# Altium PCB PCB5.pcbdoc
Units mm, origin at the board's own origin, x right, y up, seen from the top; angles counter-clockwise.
Board outline 122.68 x 122.59 mm, 2 copper layers (Top Layer, Bottom Layer); 24 components, 20 nets, 76 pads, 7 vias.
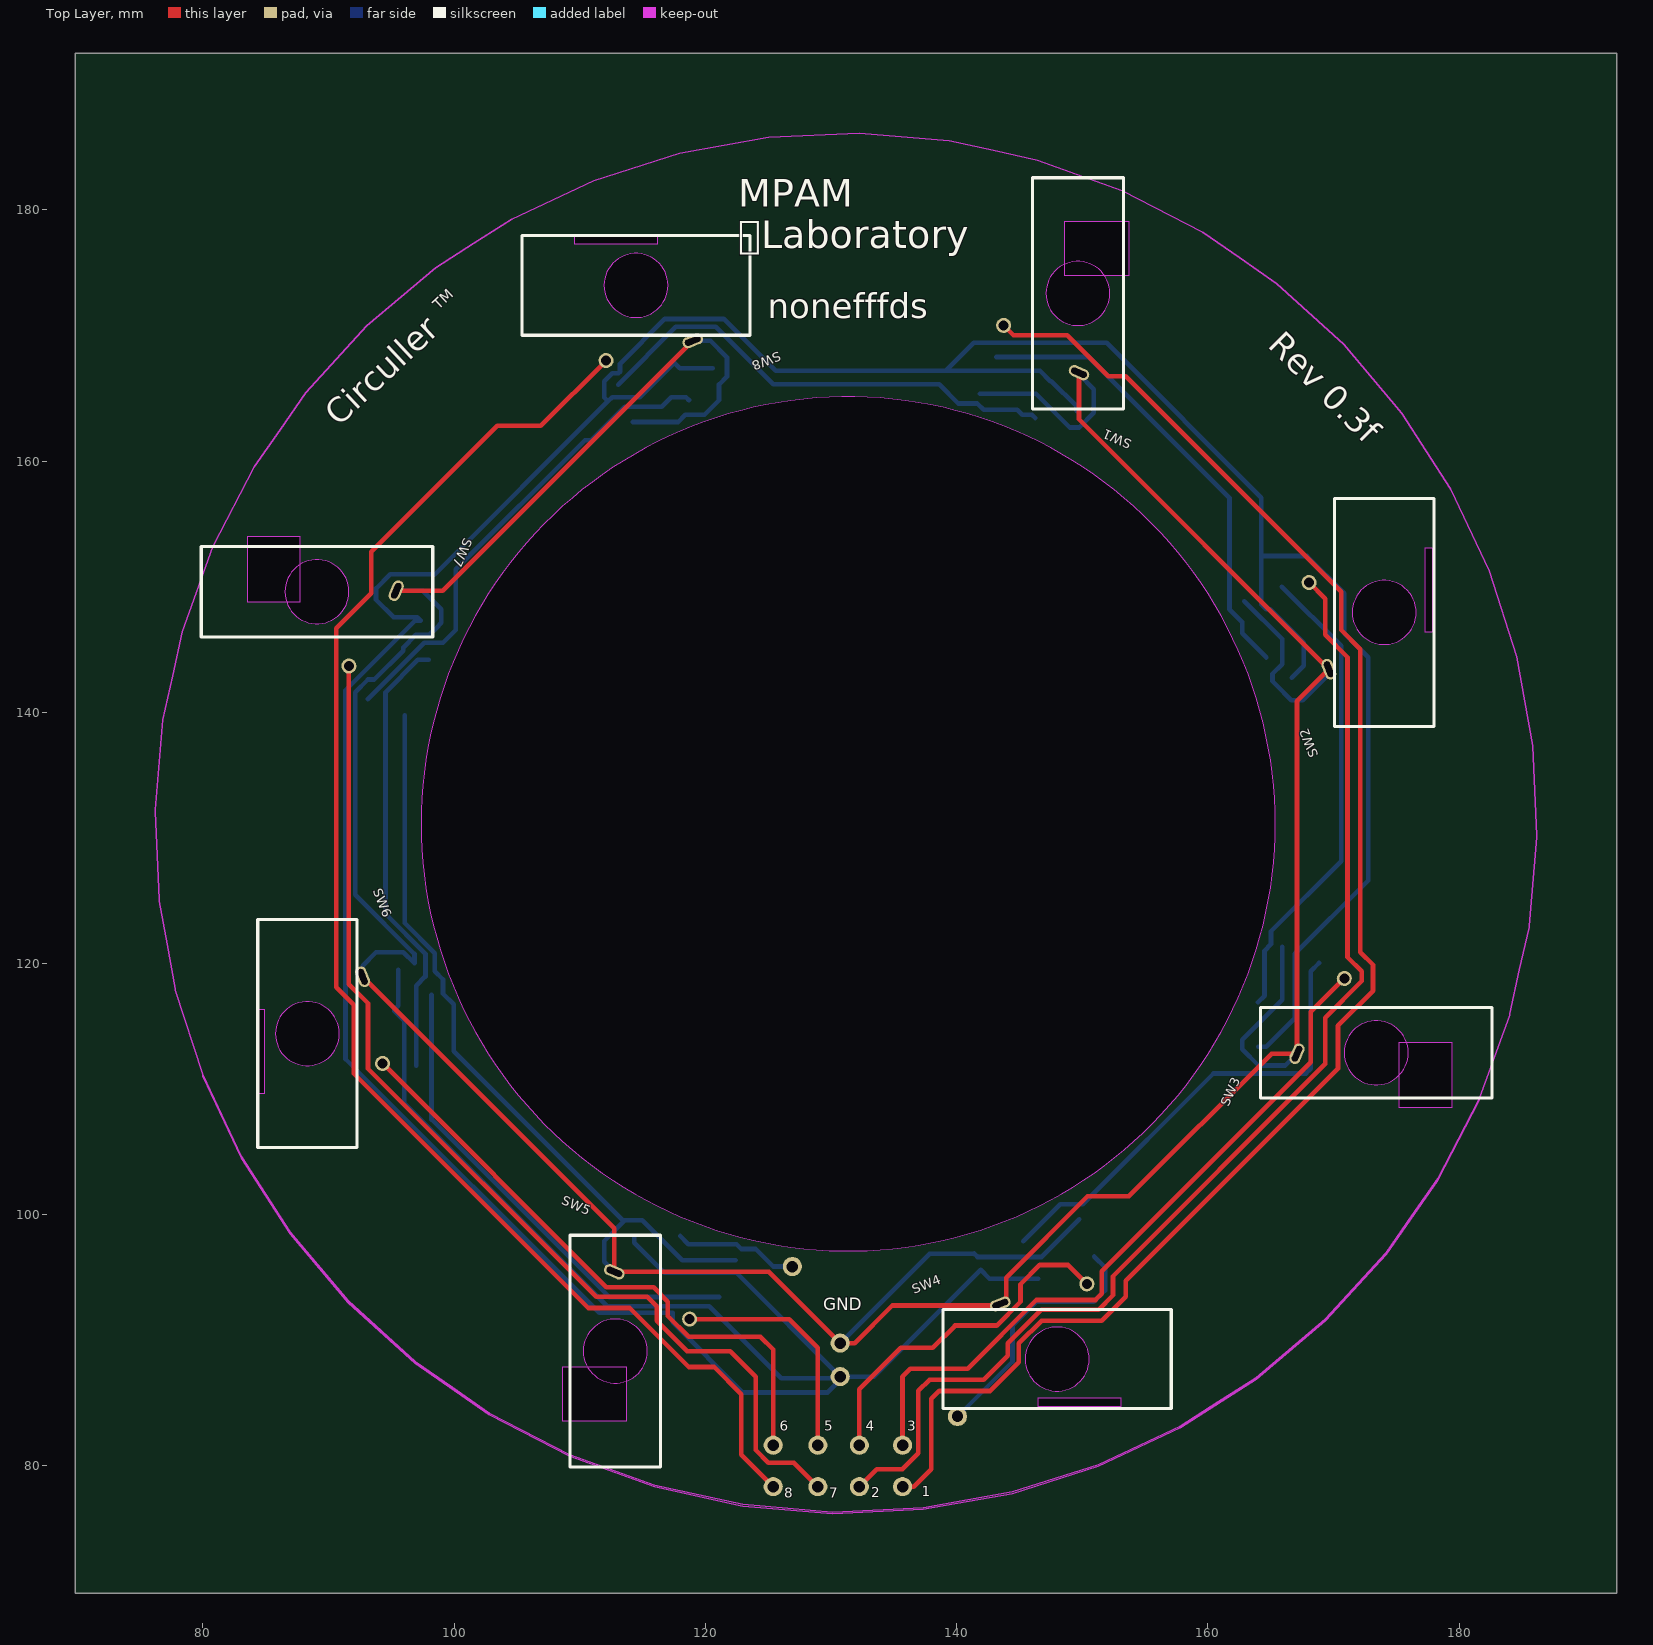
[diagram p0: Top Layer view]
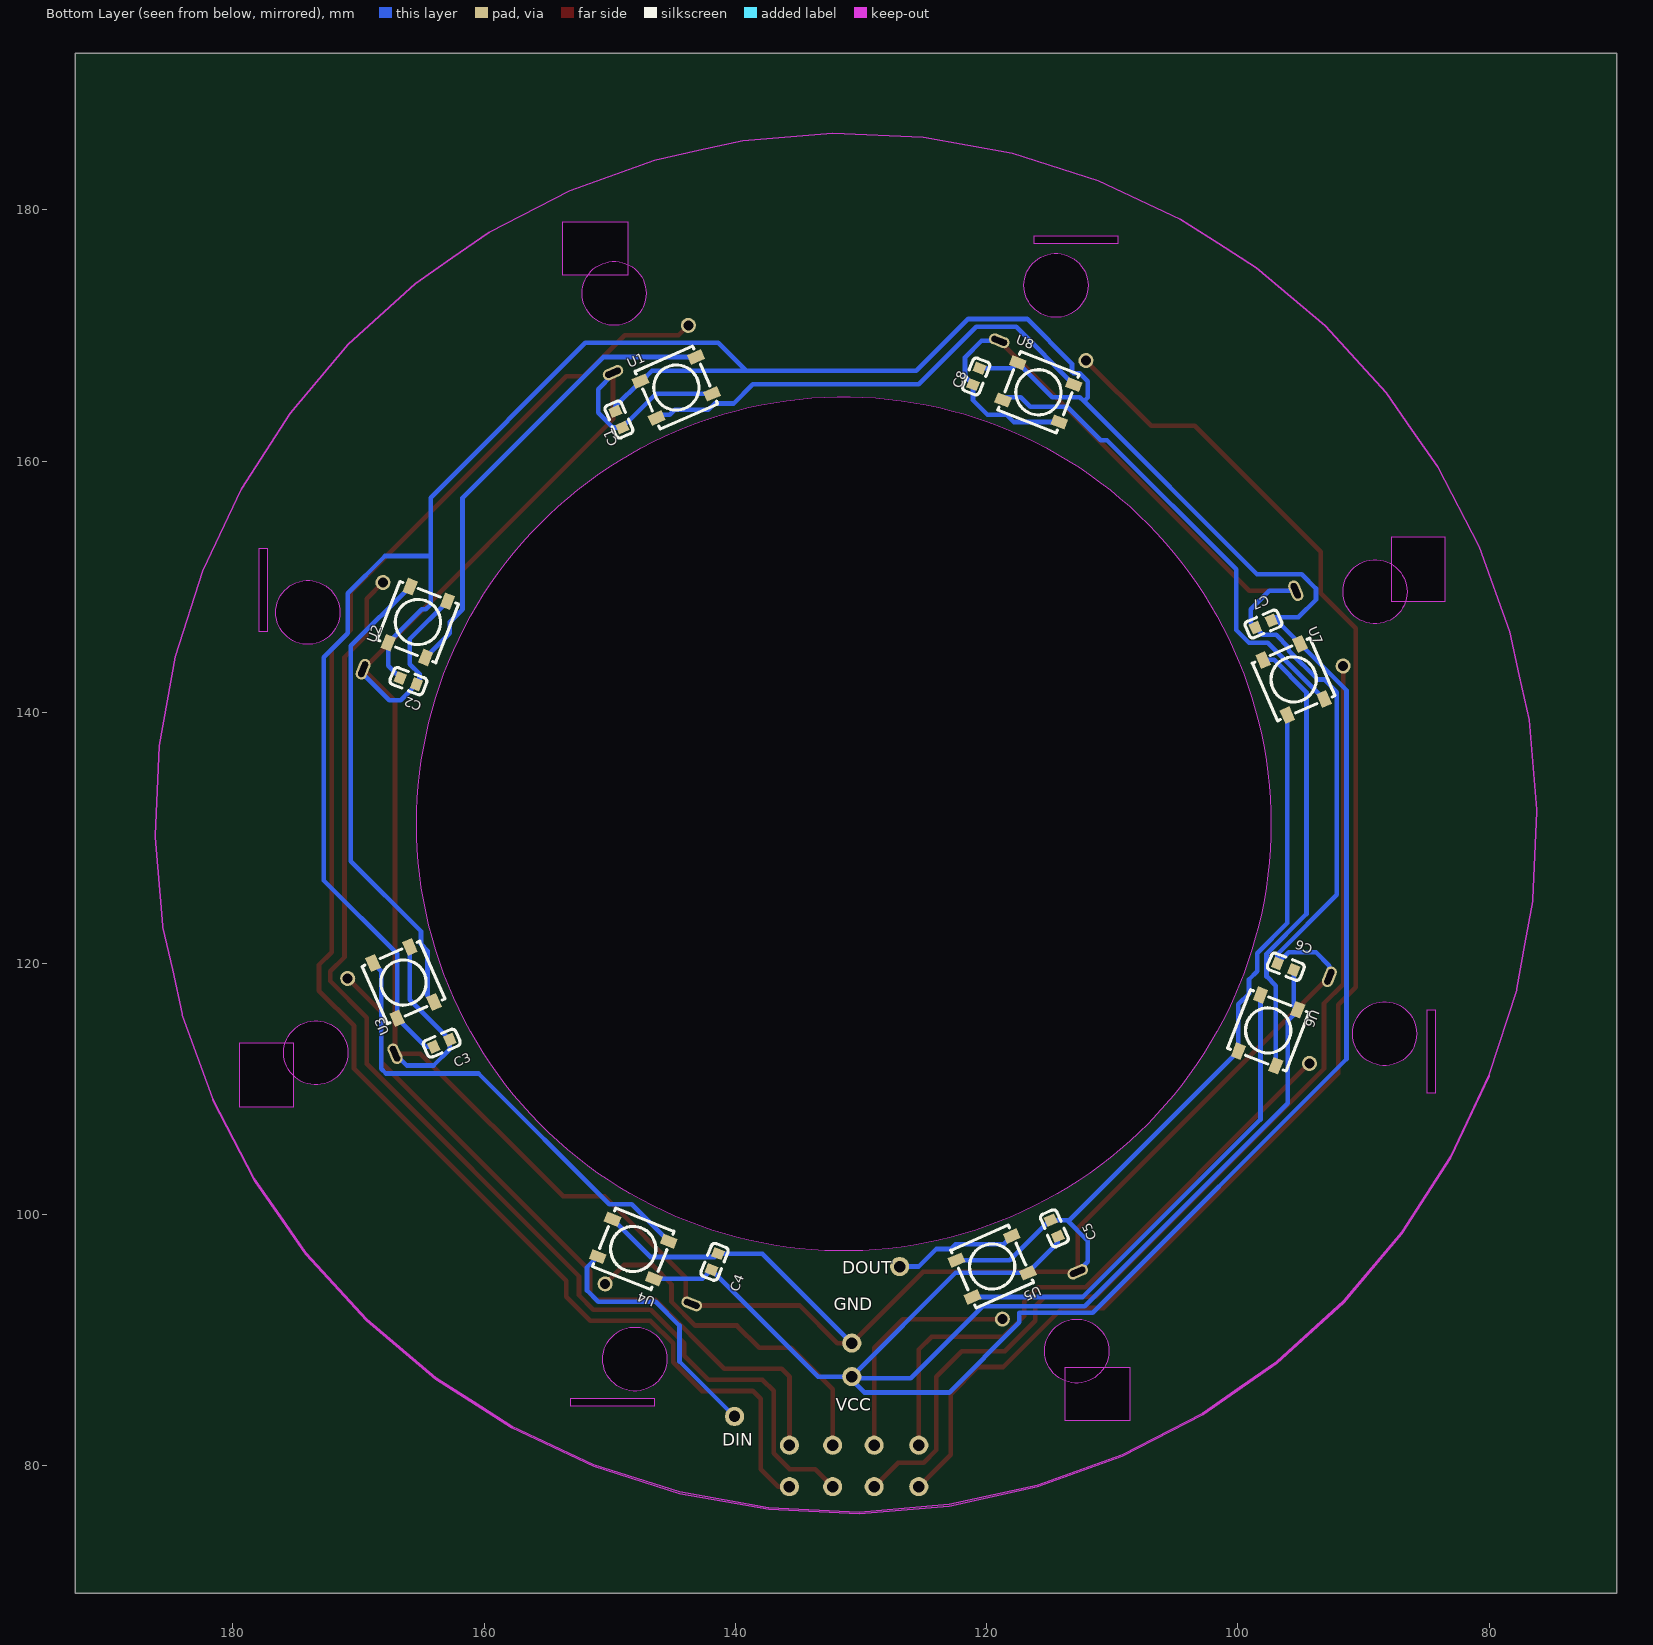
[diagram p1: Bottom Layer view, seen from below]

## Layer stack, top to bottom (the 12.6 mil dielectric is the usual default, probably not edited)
Top Layer: signal copper (thickness not stored)
Dielectric: dielectric 0.32, FR-4, Dk 4.8
Bottom Layer: signal copper (thickness not stored)

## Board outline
192.53,69.85 69.85,69.85 69.85,192.443 192.53,192.443
cut-out: 165.364,131.113 ccw(c131.364,131.113) 97.364,131.113 ccw(c131.364,131.113)
cut-out: 148.575,174.801 153.727,174.801 153.727,179.046 148.575,179.046
cut-out: 109.555,177.283 116.199,177.283 116.199,177.914 109.555,177.914
cut-out: 83.508,148.814 87.761,148.814 87.761,153.959 83.508,153.959
cut-out: 84.277,109.653 84.917,109.653 84.917,116.297 84.277,116.297
cut-out: 108.596,83.59 113.747,83.59 113.747,87.835 108.596,87.835
cut-out: 146.457,84.762 153.102,84.762 153.102,85.394 146.457,85.394
cut-out: 175.212,108.54 179.465,108.54 179.465,113.685 175.212,113.685
cut-out: 177.272,146.399 177.913,146.399 177.913,153.043 177.272,153.043

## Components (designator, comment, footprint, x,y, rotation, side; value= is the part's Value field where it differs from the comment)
C1 "CAP_0603" C0603 149.271,163.31 r66.46 bottom
C2 "CAP_0603" C0603 166.035,142.482 r21.38 bottom
C3 "CAP_0603" C0603 163.368,113.653 r156.38 bottom
C4 "CAP_0603" C0603 141.651,96.254 r111.59 bottom
C5 "CAP_0603" C0603 114.6,98.921 r66.38 bottom
C6 "CAP_0603" C0603 96.185,119.749 r21.46 bottom
C7 "CAP_0603" C0603 97.963,147.022 r336.38 bottom
C8 "CAP_0603" C0603 120.823,166.739 r111.38 bottom
SW1 "佳达隆矮轴_焊接" 佳达隆矮轴焊接#1 149.652,173.343 r156.46 top
SW2 "佳达隆矮轴_焊接" 佳达隆矮轴焊接#2 174.036,147.943 r111.38 top
SW3 "佳达隆矮轴_焊接" 佳达隆矮轴焊接#2 173.401,112.891 r66.38 top
SW4 "佳达隆矮轴_焊接" 佳达隆矮轴焊接#1 148.001,88.507 r21.59 top
SW5 "佳达隆矮轴_焊接" 佳达隆矮轴焊接#1 112.822,89.142 r336.38 top
SW6 "佳达隆矮轴_焊接" 佳达隆矮轴焊接#2 88.311,114.415 r291.46 top
SW7 "佳达隆矮轴_焊接" 佳达隆矮轴焊接#2 89.073,149.594 r246.38 top
SW8 "佳达隆矮轴_焊接" 佳达隆矮轴焊接#3 114.473,173.978 r201.38 top
U1 "5050WS2812B" LED-SMD_5050WS2812B 144.699,165.85 r156.46 bottom
U2 "5050WS2812B" LED-SMD_5050WS2812B 165.273,147.181 r111.38 bottom
U3 "5050WS2812B" LED-SMD_5050WS2812B 166.416,118.479 r66.38 bottom
U4 "5050WS2812B" LED-SMD_5050WS2812B 148.128,97.27 r21.59 bottom
U5 "5050WS2812B" LED-SMD_5050WS2812B 119.553,95.873 r336.38 bottom
U6 "5050WS2812B" LED-SMD_5050WS2812B 97.582,114.669 r291.46 bottom
U7 "5050WS2812B" LED-SMD_5050WS2812B 95.55,142.609 r246.38 bottom
U8 "5050WS2812B" LED-SMD_5050WS2812B 115.87,165.469 r201.38 bottom

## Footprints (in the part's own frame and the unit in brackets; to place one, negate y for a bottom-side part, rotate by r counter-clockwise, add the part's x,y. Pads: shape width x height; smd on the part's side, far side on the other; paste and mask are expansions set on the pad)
C0603 [mm]
  rect 0.8x0.9 smd: 1(-0.7,0) 2(0.7,0)
  silkscreen extent -1.41,-0.71 1.39,0.72
LED-SMD_5050WS2812B [mm]
  rect 1.2x0.85 smd: 1(-2.4,1.6) 2(-2.4,-1.6) 3(2.4,-1.6) 4(2.4,1.6)
  silkscreen extent -2.5,-2.5 2.5,2.5
佳达隆矮轴焊接#1 [mm]
  oval 1.7x0.9 hole 0.5 slot 1.3 at 0 deg: 1(-2.6,5.75)
  round 1.2 hole 0.8: 2(4.4,4.7)
  Multi-Layer board cut-out: -2.338,-1.019 -1.664,-1.932 -0.661,-2.463 0.473,-2.506 1.513,-2.053 2.254,-1.193 2.548,-0.097 2.338,1.019 2.338,1.019 1.664,1.932 0.661,2.463 -0.473,2.506 -1.513,2.053 -2.254,1.193 -2.548,0.097 -2.338,-1.019
  Multi-Layer keep-out region: -2.338,-1.019 -1.664,-1.932 -0.661,-2.463 0.473,-2.506 1.513,-2.053 2.254,-1.193 2.548,-0.097 2.338,1.019 2.338,1.019 1.664,1.932 0.661,2.463 -0.473,2.506 -1.513,2.053 -2.254,1.193 -2.548,0.097 -2.338,-1.019
  silkscreen extent -7,-9.89 7,9.89
佳达隆矮轴焊接#2 [mm]
  oval 1.7x0.9 hole 0.5 slot 1.3 at 0 deg: 1(-2.6,5.75)
  round 1.2 hole 0.8: 2(4.4,4.7)
  Multi-Layer board cut-out: -0.93,-2.375 0.193,-2.543 1.277,-2.207 2.108,-1.435 2.522,-0.378 2.436,0.754 1.868,1.736 0.93,2.375 0.93,2.375 -0.193,2.543 -1.277,2.207 -2.108,1.435 -2.522,0.378 -2.436,-0.754 -1.868,-1.736 -0.93,-2.375
  Multi-Layer keep-out region: -0.93,-2.375 0.193,-2.543 1.277,-2.207 2.108,-1.435 2.522,-0.378 2.436,0.754 1.868,1.736 0.93,2.375 0.93,2.375 -0.193,2.543 -1.277,2.207 -2.108,1.435 -2.522,0.378 -2.436,-0.754 -1.868,-1.736 -0.93,-2.375
  silkscreen extent -9.89,-7 9.89,7
佳达隆矮轴焊接#3 [mm]
  oval 1.7x0.9 hole 0.5 slot 1.3 at 180 deg: 1(-2.6,5.75)
  round 1.2 hole 0.8: 2(4.4,4.7)
  Multi-Layer board cut-out: -2.375,0.93 -2.543,-0.193 -2.207,-1.277 -1.435,-2.108 -0.378,-2.522 0.754,-2.436 1.736,-1.868 2.375,-0.93 2.375,-0.93 2.543,0.193 2.207,1.277 1.435,2.108 0.378,2.522 -0.754,2.436 -1.736,1.868 -2.375,0.93
  Multi-Layer keep-out region: -2.375,0.93 -2.543,-0.193 -2.207,-1.277 -1.435,-2.108 -0.378,-2.522 0.754,-2.436 1.736,-1.868 2.375,-0.93 2.375,-0.93 2.543,0.193 2.207,1.277 1.435,2.108 0.378,2.522 -0.754,2.436 -1.736,1.868 -2.375,0.93
  silkscreen extent -9.89,-7 9.89,7

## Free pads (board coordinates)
  round 1.524 hole 0.914: 1(125.395,78.347) 2(128.951,78.347) 3(132.253,78.347) 4(135.69,78.347) 5(125.395,81.649) 6(128.951,81.649) 7(132.253,81.649) 8(135.69,81.649) 9(130.729,89.777) 10(130.729,87.11) 11(126.919,95.873) 12(140.066,83.935)

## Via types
v1: diameter 0.61, hole 0.305, Top Layer to Bottom Layer, 7 vias

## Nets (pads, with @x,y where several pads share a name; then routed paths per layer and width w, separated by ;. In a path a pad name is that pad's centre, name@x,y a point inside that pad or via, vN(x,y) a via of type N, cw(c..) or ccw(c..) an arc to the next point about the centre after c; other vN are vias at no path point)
1: pad.4 SW1.2 | length 129.2
  Top Layer w0.37: pad.4 136.571,78.347 137.968,79.744 137.968,85.332 138.603,85.967 142.667,85.967 144.953,88.253 144.953,89.751 146.758,91.555 151.557,91.555 153.462,93.46 153.462,94.73 170.353,111.621 170.353,115.05 173.147,117.844 173.147,119.876 172.131,120.892 172.131,145.022 170.607,146.546 170.607,149.594 153.462,166.739 152.065,166.739 148.798,170.007 144.526,170.007 SW1.2
2: pad.6 SW5.2 | length 18.9
  Top Layer w0.37: SW5.2 126.662,91.685 128.951,89.396 pad.6
3: pad.3 SW2.2 | length 96.7
  Top Layer w0.37: pad.3 133.65,79.744 135.682,79.744 136.952,81.014 136.952,85.967 137.841,86.856 142.159,86.856 144.064,88.761 144.064,89.777 146.731,92.444 151.303,92.444 152.446,93.587 152.446,95.111 169.337,112.002 169.337,115.685 172.258,118.606 172.258,119.368 171.115,120.511 171.115,144.387 169.337,146.165 169.337,149.045 SW2.2
4: pad.5 SW6.2 | length 48.8
  Top Layer w0.37: SW6.2 112.112,94.222 115.87,94.222 117.013,93.079 117.013,91.936 118.664,90.285 124.379,90.285 125.395,89.269 pad.5
5: pad.8 SW3.2 | length 57.2
  Top Layer w0.37: pad.8 135.682,81.657 135.682,87.11 136.317,87.745 140.889,87.745 146.35,93.206 151.049,93.206 151.557,93.714 151.557,95.492 168.194,112.129 168.194,116.142 SW3.2
6: pad.2 SW7.2 | length 86.4
  Top Layer w0.37: SW7.2 91.616,118.349 93.137,116.828 93.137,111.621 111.298,93.46 115.362,93.46 116.124,92.698 116.124,91.555 118.537,89.142 121.966,89.142 123.998,87.11 123.998,81.268 125.014,80.252 127.046,80.252 pad.2
7: pad.7 SW4.2 | length 28.1
  Top Layer w0.37: pad.7 132.253,86.094 135.555,89.396 138.095,89.396 139.873,91.174 143.175,91.174 145.08,93.079 145.08,94.476 146.604,96 148.86,96 SW4.2
8: pad.1 SW8.2 | length 118.1
  Top Layer w0.37: SW8.2 106.894,162.802 103.424,162.802 93.391,152.769 93.391,149.467 90.597,146.673 90.597,118.098 91.994,116.701 91.994,111.24 110.663,92.571 113.965,92.571 118.664,87.872 120.696,87.872 122.855,85.713 122.855,80.887 pad.1
$1N1699: U1.2 U8.4 | length 38.1
  Bottom Layer w0.37: U8.4 117.644,170.676 120.823,170.676 125.395,166.104 138.603,166.104 140.127,164.58 141.651,164.58 142.159,164.072 144.826,164.072 145.207,163.691 145.994,163.691 U1.2
$1N1729: U1.4 U2.2 | length 37.2
  Bottom Layer w0.37: U1.4 150.529,168.275 161.717,157.087 161.717,148.197 162.733,147.181 162.733,146.288 U2.2
$1N1734: U2.4 U3.2 | length 37.8
  Bottom Layer w0.37: U3.2 164.511,117.444 164.511,121.019 165.019,121.527 165.019,122.543 170.607,128.131 170.607,145.28 U2.4
$1N1800: U3.4 U4.2 | length 37.3
  Bottom Layer w0.37: U4.2 148.259,100.826 150.033,100.826 160.447,111.24 167.813,111.24 168.194,111.621 168.194,119.387 U3.4
$1N1842: U6.4 U7.2 | length 35.9
  Bottom Layer w0.37: U6.4 96.971,118.225 97.711,118.965 97.711,120.763 94.534,123.94 94.534,141.593 97.108,144.167 U7.2
$1N1852: U5.4 U6.2 | length 38.7
  Bottom Layer w0.37: U6.2 98.194,107.581 112.329,93.445 U5.4
$1N6884: U7.4 U8.2 | length 38.4
  Bottom Layer w0.37: U7.4 97.602,145.53 99.106,145.53 100.122,146.546 100.122,151.372 110.409,161.659 110.917,161.659 113.584,164.326 116.505,164.326 117.267,165.088 118.455,165.088 U8.2
DIN: pad.12 U4.4 | length 20.6
  Bottom Layer w0.37: pad.12 144.445,88.314 144.445,91.174 146.35,93.079 150.922,93.079 151.811,93.968 151.811,95.803 U4.4
DOUT: pad.11 U5.2 | length 9.9
  Bottom Layer w0.37: U5.2 118.645,97.651 122.474,97.651 122.855,97.27 123.998,97.27 125.395,95.873 pad.11
GND: C1.1 C2.1 C3.2 C4.2 C5.2 C6.2 C7.2 C8.1 pad.9 SW1.1 SW2.1 SW3.1 SW4.1 SW5.1 SW6.1 SW7.1 SW8.1 U1.3 U2.3 U3.3 U4.3 U5.3 U6.3 U7.3 U8.3 | length 382.6
  Top Layer w0.37: v1(92.712,118.938) 112.744,98.905 v1(112.744,95.452) 125.054,95.452 v1(130.729,89.777) 131.872,89.777 134.865,92.77 143.341,92.77 SW4.1 143.936,93.365 143.936,94.982 150.414,101.461 153.716,101.461 165.068,112.813 SW3.1 167.091,140.887 v1(169.63,143.426) 149.739,163.316 v1(149.739,167.033) SW1.1@149.572,166.866 ; v1(95.383,149.672) 99.091,149.672 v1(118.991,169.571)
  Bottom Layer w0.37: v1(92.712,118.938) 92.712,119.831 93.772,120.892 95.95,120.892 C6.2 96.837,120.748 92.121,125.464 92.121,141.593 93.137,142.609 93.645,142.609 95.931,144.895 95.931,145.149 96.947,146.165 98.028,146.165 C7.2 98.979,147.116 98.979,148.197 97.504,149.672 v1(95.383,149.672) ; U7.3 96.055,123.221 98.45,120.825 98.45,119.379 99.106,118.723 99.106,117.59 99.949,116.747 U6.3 113.407,99.562 113.591,99.562 ; v1(112.744,95.452) 111.933,96.263 111.933,97.905 113.591,99.562 ; U8.3 117.824,163.104 118.399,163.68 119.923,163.68 121.077,164.834 C8.1@121.077,166.086 ; v1(118.991,169.571) 120.404,169.571 121.712,168.263 121.712,166.721 C8.1 ; U5.3 118.16,96.377 114.975,99.562 C5.2 113.591,99.562 ; v1(130.729,89.777) 137.841,96.889 141.378,96.889 C4.2 141.664,96.635 146.766,96.635 U4.3 ; U1.3 146.318,165.342 C1.1 149.749,162.668 150.922,163.841 150.922,165.723 149.739,166.906 v1(149.739,167.033) ; U2.3 165.908,145.833 165.908,143.824 165.146,143.062 165.146,142.464 C2.1 166.652,140.958 167.559,140.958 169.63,143.028 v1(169.63,143.426) ; U3.3 165.912,117.119 C3.2 162.727,113.176 164.028,111.875 166.153,111.875 SW3.1
VCC: C1.2 C2.2 C3.1 C4.1 C5.1 C6.1 C7.1 C8.2 pad.10 U1.1 U2.1 U3.1 U4.1 U5.1 U6.1 U7.1 U8.1 | length 365.8
  Bottom Layer w0.37: C6.1 95.534,116.636 U6.1 95.215,116.219 96.015,115.419 96.015,108.87 112.187,92.698 120.315,92.698 126.03,86.983 130.602,86.983 pad.10 ; C5.1 114.32,97.762 U5.1 122.471,95.369 pad.10 ; C8.2 117.965,167.391 U8.1 114.776,165.088 112.568,165.088 112.236,164.756 ; U4.1 142.613,94.899 C4.1 133.416,87.11 pad.10 ; C1.2 149.551,164.346 U1.1 147.448,166.358 146.634,167.172 139.142,167.172 ; C3.1 164.654,113.372 U3.1 166.921,120.761 172.766,126.607 172.766,144.387 170.861,146.292 170.861,149.467 167.89,152.438 164.257,152.438 ; C2.2 167.638,143.688 U2.1 164.971,148.197 164.638,148.197 164.257,148.578 164.257,152.438 ; 112.236,164.756 111.933,165.059 111.933,166.358 112.568,166.993 113.076,166.993 113.203,167.12 113.203,167.755 116.759,171.311 121.458,171.311 125.597,167.172 139.142,167.172 ; 112.236,164.756 98.471,150.991 94.915,150.991 93.772,149.848 93.772,148.959 95.169,147.562 97.063,147.562 C7.1 96.9,147.303 U7.1 91.346,141.749 91.346,112.396 111.552,92.19 117.394,92.19 117.394,91.428 122.982,85.84 129.713,85.84 130.729,86.856 pad.10 ; 139.142,167.172 141.376,169.406 151.938,169.406 164.257,157.087 164.257,152.438
"": 

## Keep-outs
Board Outline Layer:
  lines w0.1 net "": 79.988,111.163 77.805,117.881 77.805,118.005 77.17,121.539 76.535,124.948 76.535,125.072 76.2,132.121 76.2,132.245 76.806,139.4 77.574,142.908 78.343,146.415 80.783,153.17 84.087,159.548 86.141,162.495 88.196,165.442 93.041,170.751 98.538,175.382 101.567,177.32 104.595,179.258 111.106,182.312 117.961,184.491 121.502,185.125 125.042,185.758 132.229,186.093 139.398,185.488 142.912,184.721 146.426,183.954 153.194,181.518 159.585,178.221 162.537,176.17 165.49,174.12 170.809,169.284 175.449,163.797 177.391,160.775 179.332,157.753 182.392,151.254 184.575,144.412 185.21,140.878 185.845,137.344 186.18,130.171 186.18,130.047 185.574,123.016 185.574,122.893 184.806,119.509 184.038,116.002 184.038,115.878 181.597,109.247 ; 79.988,111.163 83.048,104.664 84.989,101.642 86.931,98.619 91.572,93.132 96.89,88.297 99.843,86.246 102.795,84.196 109.187,80.899 115.954,78.462 119.468,77.696 122.982,76.929 130.151,76.324 137.338,76.658 140.878,77.292 144.419,77.926 151.274,80.105 157.785,83.159 160.814,85.097 163.842,87.034 169.339,91.666 174.184,96.974 176.239,99.921 178.293,102.868 181.597,109.247 ; 79.988,111.163 79.988,111.039 83.048,104.54 86.931,98.495 91.572,93.008 96.89,88.173 102.795,84.072 109.187,80.775 115.954,78.338 122.982,76.805 130.151,76.2 137.338,76.534 144.419,77.802 151.274,79.981 157.785,83.035 163.842,86.91 169.339,91.542 174.184,96.85 178.293,102.744 181.597,109.123 181.597,109.247
Multi-Layer:
  region net "": 165.364,131.113 ccw(c131.364,131.113) 97.364,131.113 ccw(c131.364,131.113)
  region net "": 148.575,174.801 153.727,174.801 153.727,179.046 148.575,179.046
  region net "": 109.555,177.283 116.199,177.283 116.199,177.914 109.555,177.914
  region net "": 83.508,148.814 87.761,148.814 87.761,153.959 83.508,153.959
  region net "": 84.277,109.653 84.917,109.653 84.917,116.297 84.277,116.297
  region net "": 108.596,83.59 113.747,83.59 113.747,87.835 108.596,87.835
  region net "": 146.457,84.762 153.102,84.762 153.102,85.394 146.457,85.394
  region net "": 175.212,108.54 179.465,108.54 179.465,113.685 175.212,113.685
  region net "": 177.272,146.399 177.913,146.399 177.913,153.043 177.272,153.043

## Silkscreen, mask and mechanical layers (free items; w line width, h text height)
Top Silkscreen Layer:
  text "MPAM  /  Laboratory" at 122.631,176.941 h2.21
  text "TM" at 98.757,172.006 h0.84 r43.09
  text "nonefffds" at 124.959,171.353 h1.98
  text "Rev 0.3f" at 164.69,169.154 h1.95 r315
  text "Circuller" at 90.789,162.697 h1.95 r43.09
  text "GND" at 129.376,92.396 h0.97
  text "6" at 125.903,82.801 h0.78
  text "5" at 129.459,82.801 h0.78
  text "4" at 132.761,82.801 h0.78
  text "3" at 136.063,82.801 h0.78
  text "1" at 137.206,77.594 h0.78
  text "2" at 133.203,77.502 h0.78
  text "8" at 126.284,77.467 h0.78
  text "7" at 129.84,77.467 h0.78
Bottom Silkscreen Layer:
  text "DOUT" at 131.493,95.317 h0.97
  text "GND" at 132.17,92.396 h0.97
  text "VCC" at 132.017,84.407 h0.97
  text "DIN" at 141.06,81.601 h0.97
Mechanical Layer:
  circle w0.025 net "": c131.364,131.113 r34
  lines w0.025 net "": 83.508,148.814 87.761,148.814 87.761,153.959 83.508,153.959 83.508,148.814 ; 84.277,109.653 84.917,109.653 84.917,116.297 84.277,116.297 84.277,109.653 ; 108.596,83.59 113.747,83.59 113.747,87.835 108.596,87.835 108.596,83.59 ; 109.555,177.283 116.199,177.283 116.199,177.914 109.555,177.914 109.555,177.283 ; 146.457,84.762 153.102,84.762 153.102,85.394 146.457,85.394 146.457,84.762 ; 148.575,174.801 153.727,174.801 153.727,179.046 148.575,179.046 148.575,174.801 ; 175.212,108.54 179.465,108.54 179.465,113.685 175.212,113.685 175.212,108.54 ; 177.272,146.399 177.913,146.399 177.913,153.043 177.272,153.043 177.272,146.399
Mech6:
  lines w0.1 net "": 78.646,118.678 84.123,104.741 98.087,110.208 92.61,124.145 78.646,118.678 ; 79.157,145.71 85.158,159.431 98.906,153.442 92.905,139.721 79.157,145.71 ; 102.913,85.265 108.914,98.986 122.661,92.997 116.66,79.276 102.913,85.265 ; 104.672,178.185 118.636,183.652 124.113,169.714 110.149,164.247 104.672,178.185 ; 138.267,92.703 152.231,98.169 157.708,84.232 143.744,78.765 138.267,92.703 ; 139.719,169.42 153.466,163.431 159.467,177.152 145.72,183.141 139.719,169.42 ; 163.475,108.975 177.222,102.985 183.223,116.706 169.475,122.696 163.475,108.975 ; 164.293,152.209 169.77,138.272 183.734,143.738 178.257,157.676 164.293,152.209
Mech15:
  lines w0.1 net "": 97.196,131.849 97.571,136.148 97.571,136.272 98.046,138.441 98.521,140.485 98.521,140.609 100.03,144.66 102.072,148.604 104.612,152.247 107.607,155.529 111.005,158.392 114.749,160.788 118.775,162.675 123.012,164.023 127.39,164.806 131.832,165.013 136.264,164.639 140.609,163.691 144.792,162.185 148.743,160.147 152.394,157.611 155.681,154.622 158.55,151.23 160.951,147.494 162.842,143.476 164.192,139.371 164.192,139.247 164.584,137.186 164.977,135.001 164.977,134.877 165.184,130.567 164.809,126.144 164.334,123.976 163.859,121.808 162.351,117.632 160.309,113.689 159.038,111.867 157.768,110.045 154.773,106.764 151.375,103.901 149.503,102.703 147.631,101.505 143.606,99.617 139.368,98.27 137.179,97.878 134.99,97.486 130.548,97.28 126.116,97.654 123.944,98.128 121.771,98.602 117.588,100.108 113.637,102.146 111.812,103.414 109.986,104.681 106.699,107.67 103.83,111.062 102.63,112.931 101.429,114.799 99.538,118.817 98.188,123.046 97.796,125.231 97.403,127.415 97.196,131.849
